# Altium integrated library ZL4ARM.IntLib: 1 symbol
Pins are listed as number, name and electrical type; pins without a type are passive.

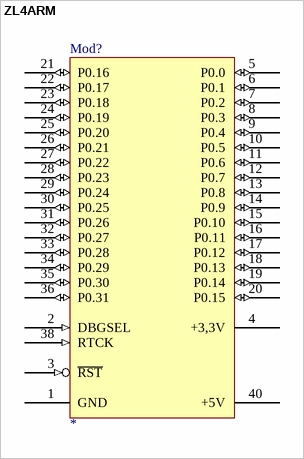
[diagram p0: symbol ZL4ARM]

## ZL4ARM
designator Mod?
www.btc.pl
footprint ZL4ARM
pins: 1 GND (power), 2 DBGSEL (in), 3 ~{RST} (in), 4 +3,3V (power), 5 P0.0 (io), 6 P0.1 (io), 7 P0.2 (io), 8 P0.3 (io), 9 P0.4 (io), 10 P0.5 (io), 11 P0.6 (io), 12 P0.7 (io), 13 P0.8 (io), 14 P0.9 (io), 15 P0.10 (io), 16 P0.11 (io), 17 P0.12 (io), 18 P0.13 (io), 19 P0.14 (io), 20 P0.15 (io), 21 P0.16 (io), 22 P0.17 (io), 23 P0.18 (io), 24 P0.19 (io), 25 P0.20 (io), 26 P0.21 (io), 27 P0.22 (io), 28 P0.23 (io), 29 P0.24 (io), 30 P0.25 (io), 31 P0.26 (io), 32 P0.27 (io), 33 P0.28 (io), 34 P0.29 (io), 35 P0.30 (io), 36 P0.31 (io), 38 RTCK (in), 40 +5V (power)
